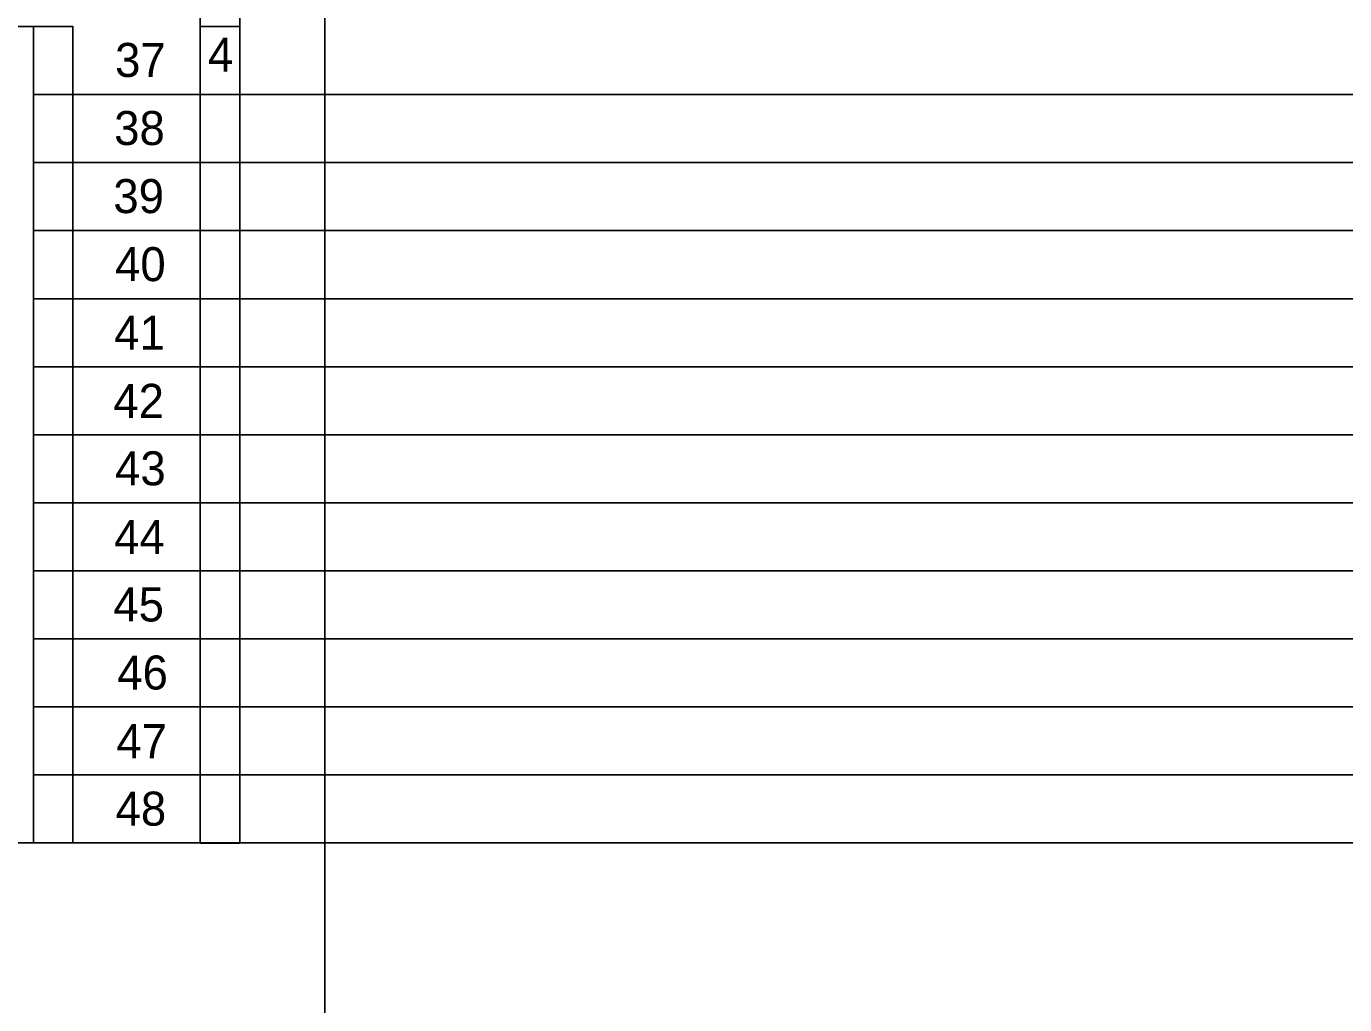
# Model space of a CAD drawing. Extents: x 1901 to 2519, y -3585 to -3154.
# Drawn here: x 2113 to 2181.2, y -3380.3 to -3329.7 of the extents above; entities that cross this region are included whole.
import ezdxf

# ---------------------------------------------------------------- set-up
doc = ezdxf.new("R2010")
doc.units = 0
doc.layers.add('rozvláknění', color=7, linetype='Continuous')

msp = doc.modelspace()

# ---------------------------------------------------------------- linework, layer by layer
at = {"layer": 'rozvláknění'}
for p, q in [((2115.435, -3333.247), (2247.063, -3333.246)), ((2115.435, -3336.765), (2247.063, -3336.764)), ((2115.435, -3340.283), (2247.063, -3340.282)), ((2115.435, -3343.801), (2247.063, -3343.8)), ((2115.435, -3347.319), (2247.063, -3347.318)), ((2115.435, -3350.837), (2247.063, -3350.837)), ((2115.435, -3354.356), (2247.063, -3354.355)), ((2115.435, -3357.874), (2247.063, -3357.873)), ((2115.435, -3361.392), (2247.063, -3361.391)), ((2115.435, -3364.91), (2247.063, -3364.909)), ((2115.435, -3368.428), (2247.063, -3368.428)), ((2115.435, -3371.947), (2247.063, -3371.946))]:
    msp.add_line(p, q, dxfattribs=at)
for points in [[(2094.462, -3178.545), (2128.46, -3178.544), (2128.46, -3571.465), (2094.462, -3571.465)], [(2124.059, -3371.961), (2122.017, -3371.961), (2122.017, -3287.488), (2124.059, -3287.488)], [(2110.606, -3329.728), (2113.393, -3329.728), (2113.393, -3371.943), (2110.606, -3371.943)], [(2113.393, -3329.728), (2115.435, -3329.728), (2115.435, -3333.247), (2113.393, -3333.247)], [(2113.393, -3329.728), (2115.435, -3329.728), (2115.435, -3333.247), (2113.393, -3333.247)], [(2124.059, -3371.947), (2122.017, -3371.947), (2122.017, -3329.728), (2124.059, -3329.728)], [(2113.393, -3333.247), (2115.435, -3333.247), (2115.435, -3336.765), (2113.393, -3336.765)], [(2113.393, -3333.247), (2115.435, -3333.247), (2115.435, -3336.765), (2113.393, -3336.765)], [(2113.393, -3336.765), (2115.435, -3336.765), (2115.435, -3340.283), (2113.393, -3340.283)], [(2113.393, -3336.765), (2115.435, -3336.765), (2115.435, -3340.283), (2113.393, -3340.283)], [(2113.393, -3340.283), (2115.435, -3340.283), (2115.435, -3343.801), (2113.393, -3343.801)], [(2113.393, -3340.283), (2115.435, -3340.283), (2115.435, -3343.801), (2113.393, -3343.801)], [(2113.393, -3343.801), (2115.435, -3343.801), (2115.435, -3347.319), (2113.393, -3347.319)], [(2113.393, -3343.801), (2115.435, -3343.801), (2115.435, -3347.319), (2113.393, -3347.319)], [(2113.393, -3347.319), (2115.435, -3347.319), (2115.435, -3350.837), (2113.393, -3350.837)], [(2113.393, -3347.319), (2115.435, -3347.319), (2115.435, -3350.837), (2113.393, -3350.837)], [(2113.393, -3350.837), (2115.435, -3350.837), (2115.435, -3354.356), (2113.393, -3354.356)], [(2113.393, -3350.837), (2115.435, -3350.837), (2115.435, -3354.356), (2113.393, -3354.356)], [(2113.393, -3354.356), (2115.435, -3354.356), (2115.435, -3357.874), (2113.393, -3357.874)], [(2113.393, -3354.356), (2115.435, -3354.356), (2115.435, -3357.874), (2113.393, -3357.874)], [(2113.393, -3357.874), (2115.435, -3357.874), (2115.435, -3361.392), (2113.393, -3361.392)], [(2113.393, -3357.874), (2115.435, -3357.874), (2115.435, -3361.392), (2113.393, -3361.392)], [(2113.393, -3361.392), (2115.435, -3361.392), (2115.435, -3364.91), (2113.393, -3364.91)], [(2113.393, -3361.392), (2115.435, -3361.392), (2115.435, -3364.91), (2113.393, -3364.91)], [(2113.393, -3364.91), (2115.435, -3364.91), (2115.435, -3368.428), (2113.393, -3368.428)], [(2113.393, -3364.91), (2115.435, -3364.91), (2115.435, -3368.428), (2113.393, -3368.428)], [(2113.393, -3368.428), (2115.435, -3368.428), (2115.435, -3371.947), (2113.393, -3371.947)], [(2113.393, -3368.428), (2115.435, -3368.428), (2115.435, -3371.947), (2113.393, -3371.947)]]:
    msp.add_lwpolyline(points, close=True, dxfattribs=at)
for points in [[(2113.393, -3333.247), (2115.435, -3333.247), (2115.435, -3329.728), (2113.393, -3329.728), (2113.393, -3333.247)], [(2113.393, -3333.247), (2115.435, -3333.247), (2115.435, -3329.728), (2113.393, -3329.728), (2113.393, -3333.247)], [(2113.393, -3333.247), (2115.435, -3333.247), (2115.435, -3329.728), (2113.393, -3329.728), (2113.393, -3333.247)], [(2113.393, -3333.247), (2115.435, -3333.247), (2115.435, -3329.728), (2113.393, -3329.728), (2113.393, -3333.247)], [(2113.393, -3333.247), (2115.435, -3333.247), (2115.435, -3329.728), (2113.393, -3329.728), (2113.393, -3333.247)], [(2113.393, -3333.247), (2115.435, -3333.247), (2115.435, -3329.728), (2113.393, -3329.728), (2113.393, -3333.247)], [(2113.393, -3333.247), (2115.435, -3333.247), (2115.435, -3329.728), (2113.393, -3329.728), (2113.393, -3333.247)], [(2113.393, -3333.247), (2115.435, -3333.247), (2115.435, -3329.728), (2113.393, -3329.728), (2113.393, -3333.247)], [(2113.393, -3333.247), (2115.435, -3333.247), (2115.435, -3329.728), (2113.393, -3329.728), (2113.393, -3333.247)], [(2113.393, -3333.247), (2115.435, -3333.247), (2115.435, -3329.728), (2113.393, -3329.728), (2113.393, -3333.247)], [(2124.059, -3329.728), (2122.017, -3329.728), (2122.017, -3371.947), (2124.059, -3371.947), (2124.059, -3329.728)], [(2124.059, -3329.728), (2122.017, -3329.728), (2122.017, -3371.947), (2124.059, -3371.947), (2124.059, -3329.728)], [(2124.059, -3329.728), (2122.017, -3329.728), (2122.017, -3371.947), (2124.059, -3371.947), (2124.059, -3329.728)], [(2124.059, -3329.728), (2122.017, -3329.728), (2122.017, -3371.947), (2124.059, -3371.947), (2124.059, -3329.728)], [(2124.059, -3329.728), (2122.017, -3329.728), (2122.017, -3371.947), (2124.059, -3371.947), (2124.059, -3329.728)], [(2124.059, -3329.728), (2122.017, -3329.728), (2122.017, -3371.947), (2124.059, -3371.947), (2124.059, -3329.728)], [(2113.393, -3333.244), (2113.393, -3368.444)], [(2113.393, -3336.765), (2115.435, -3336.765), (2115.435, -3333.247), (2113.393, -3333.247), (2113.393, -3336.765)], [(2113.393, -3336.765), (2115.435, -3336.765), (2115.435, -3333.247), (2113.393, -3333.247), (2113.393, -3336.765)], [(2113.393, -3336.765), (2115.435, -3336.765), (2115.435, -3333.247), (2113.393, -3333.247), (2113.393, -3336.765)], [(2113.393, -3336.765), (2115.435, -3336.765), (2115.435, -3333.247), (2113.393, -3333.247), (2113.393, -3336.765)], [(2113.393, -3336.765), (2115.435, -3336.765), (2115.435, -3333.247), (2113.393, -3333.247), (2113.393, -3336.765)], [(2113.393, -3336.765), (2115.435, -3336.765), (2115.435, -3333.247), (2113.393, -3333.247), (2113.393, -3336.765)], [(2113.393, -3336.765), (2115.435, -3336.765), (2115.435, -3333.247), (2113.393, -3333.247), (2113.393, -3336.765)], [(2113.393, -3336.765), (2115.435, -3336.765), (2115.435, -3333.247), (2113.393, -3333.247), (2113.393, -3336.765)], [(2113.393, -3336.765), (2115.435, -3336.765), (2115.435, -3333.247), (2113.393, -3333.247), (2113.393, -3336.765)], [(2113.393, -3336.765), (2115.435, -3336.765), (2115.435, -3333.247), (2113.393, -3333.247), (2113.393, -3336.765)], [(2113.393, -3340.283), (2115.435, -3340.283), (2115.435, -3336.765), (2113.393, -3336.765), (2113.393, -3340.283)], [(2113.393, -3340.283), (2115.435, -3340.283), (2115.435, -3336.765), (2113.393, -3336.765), (2113.393, -3340.283)], [(2113.393, -3340.283), (2115.435, -3340.283), (2115.435, -3336.765), (2113.393, -3336.765), (2113.393, -3340.283)], [(2113.393, -3340.283), (2115.435, -3340.283), (2115.435, -3336.765), (2113.393, -3336.765), (2113.393, -3340.283)], [(2113.393, -3340.283), (2115.435, -3340.283), (2115.435, -3336.765), (2113.393, -3336.765), (2113.393, -3340.283)], [(2113.393, -3340.283), (2115.435, -3340.283), (2115.435, -3336.765), (2113.393, -3336.765), (2113.393, -3340.283)], [(2113.393, -3340.283), (2115.435, -3340.283), (2115.435, -3336.765), (2113.393, -3336.765), (2113.393, -3340.283)], [(2113.393, -3340.283), (2115.435, -3340.283), (2115.435, -3336.765), (2113.393, -3336.765), (2113.393, -3340.283)], [(2113.393, -3340.283), (2115.435, -3340.283), (2115.435, -3336.765), (2113.393, -3336.765), (2113.393, -3340.283)], [(2113.393, -3340.283), (2115.435, -3340.283), (2115.435, -3336.765), (2113.393, -3336.765), (2113.393, -3340.283)], [(2113.393, -3343.801), (2115.435, -3343.801), (2115.435, -3340.283), (2113.393, -3340.283), (2113.393, -3343.801)], [(2113.393, -3343.801), (2115.435, -3343.801), (2115.435, -3340.283), (2113.393, -3340.283), (2113.393, -3343.801)], [(2113.393, -3343.801), (2115.435, -3343.801), (2115.435, -3340.283), (2113.393, -3340.283), (2113.393, -3343.801)], [(2113.393, -3343.801), (2115.435, -3343.801), (2115.435, -3340.283), (2113.393, -3340.283), (2113.393, -3343.801)], [(2113.393, -3343.801), (2115.435, -3343.801), (2115.435, -3340.283), (2113.393, -3340.283), (2113.393, -3343.801)], [(2113.393, -3343.801), (2115.435, -3343.801), (2115.435, -3340.283), (2113.393, -3340.283), (2113.393, -3343.801)], [(2113.393, -3343.801), (2115.435, -3343.801), (2115.435, -3340.283), (2113.393, -3340.283), (2113.393, -3343.801)], [(2113.393, -3343.801), (2115.435, -3343.801), (2115.435, -3340.283), (2113.393, -3340.283), (2113.393, -3343.801)], [(2113.393, -3343.801), (2115.435, -3343.801), (2115.435, -3340.283), (2113.393, -3340.283), (2113.393, -3343.801)], [(2113.393, -3343.801), (2115.435, -3343.801), (2115.435, -3340.283), (2113.393, -3340.283), (2113.393, -3343.801)], [(2113.393, -3347.319), (2115.435, -3347.319), (2115.435, -3343.801), (2113.393, -3343.801), (2113.393, -3347.319)], [(2113.393, -3347.319), (2115.435, -3347.319), (2115.435, -3343.801), (2113.393, -3343.801), (2113.393, -3347.319)], [(2113.393, -3347.319), (2115.435, -3347.319), (2115.435, -3343.801), (2113.393, -3343.801), (2113.393, -3347.319)], [(2113.393, -3347.319), (2115.435, -3347.319), (2115.435, -3343.801), (2113.393, -3343.801), (2113.393, -3347.319)], [(2113.393, -3347.319), (2115.435, -3347.319), (2115.435, -3343.801), (2113.393, -3343.801), (2113.393, -3347.319)], [(2113.393, -3347.319), (2115.435, -3347.319), (2115.435, -3343.801), (2113.393, -3343.801), (2113.393, -3347.319)], [(2113.393, -3347.319), (2115.435, -3347.319), (2115.435, -3343.801), (2113.393, -3343.801), (2113.393, -3347.319)], [(2113.393, -3347.319), (2115.435, -3347.319), (2115.435, -3343.801), (2113.393, -3343.801), (2113.393, -3347.319)], [(2113.393, -3347.319), (2115.435, -3347.319), (2115.435, -3343.801), (2113.393, -3343.801), (2113.393, -3347.319)], [(2113.393, -3347.319), (2115.435, -3347.319), (2115.435, -3343.801), (2113.393, -3343.801), (2113.393, -3347.319)], [(2113.393, -3350.837), (2115.435, -3350.837), (2115.435, -3347.319), (2113.393, -3347.319), (2113.393, -3350.837)], [(2113.393, -3350.837), (2115.435, -3350.837), (2115.435, -3347.319), (2113.393, -3347.319), (2113.393, -3350.837)], [(2113.393, -3350.837), (2115.435, -3350.837), (2115.435, -3347.319), (2113.393, -3347.319), (2113.393, -3350.837)], [(2113.393, -3350.837), (2115.435, -3350.837), (2115.435, -3347.319), (2113.393, -3347.319), (2113.393, -3350.837)], [(2113.393, -3350.837), (2115.435, -3350.837), (2115.435, -3347.319), (2113.393, -3347.319), (2113.393, -3350.837)], [(2113.393, -3350.837), (2115.435, -3350.837), (2115.435, -3347.319), (2113.393, -3347.319), (2113.393, -3350.837)], [(2113.393, -3350.837), (2115.435, -3350.837), (2115.435, -3347.319), (2113.393, -3347.319), (2113.393, -3350.837)], [(2113.393, -3350.837), (2115.435, -3350.837), (2115.435, -3347.319), (2113.393, -3347.319), (2113.393, -3350.837)], [(2113.393, -3350.837), (2115.435, -3350.837), (2115.435, -3347.319), (2113.393, -3347.319), (2113.393, -3350.837)], [(2113.393, -3350.837), (2115.435, -3350.837), (2115.435, -3347.319), (2113.393, -3347.319), (2113.393, -3350.837)], [(2113.393, -3354.356), (2115.435, -3354.356), (2115.435, -3350.837), (2113.393, -3350.837), (2113.393, -3354.356)], [(2113.393, -3354.356), (2115.435, -3354.356), (2115.435, -3350.837), (2113.393, -3350.837), (2113.393, -3354.356)], [(2113.393, -3354.356), (2115.435, -3354.356), (2115.435, -3350.837), (2113.393, -3350.837), (2113.393, -3354.356)], [(2113.393, -3354.356), (2115.435, -3354.356), (2115.435, -3350.837), (2113.393, -3350.837), (2113.393, -3354.356)], [(2113.393, -3354.356), (2115.435, -3354.356), (2115.435, -3350.837), (2113.393, -3350.837), (2113.393, -3354.356)], [(2113.393, -3354.356), (2115.435, -3354.356), (2115.435, -3350.837), (2113.393, -3350.837), (2113.393, -3354.356)], [(2113.393, -3354.356), (2115.435, -3354.356), (2115.435, -3350.837), (2113.393, -3350.837), (2113.393, -3354.356)], [(2113.393, -3354.356), (2115.435, -3354.356), (2115.435, -3350.837), (2113.393, -3350.837), (2113.393, -3354.356)], [(2113.393, -3354.356), (2115.435, -3354.356), (2115.435, -3350.837), (2113.393, -3350.837), (2113.393, -3354.356)], [(2113.393, -3354.356), (2115.435, -3354.356), (2115.435, -3350.837), (2113.393, -3350.837), (2113.393, -3354.356)], [(2113.393, -3357.874), (2115.435, -3357.874), (2115.435, -3354.356), (2113.393, -3354.356), (2113.393, -3357.874)], [(2113.393, -3357.874), (2115.435, -3357.874), (2115.435, -3354.356), (2113.393, -3354.356), (2113.393, -3357.874)], [(2113.393, -3357.874), (2115.435, -3357.874), (2115.435, -3354.356), (2113.393, -3354.356), (2113.393, -3357.874)], [(2113.393, -3357.874), (2115.435, -3357.874), (2115.435, -3354.356), (2113.393, -3354.356), (2113.393, -3357.874)], [(2113.393, -3357.874), (2115.435, -3357.874), (2115.435, -3354.356), (2113.393, -3354.356), (2113.393, -3357.874)], [(2113.393, -3357.874), (2115.435, -3357.874), (2115.435, -3354.356), (2113.393, -3354.356), (2113.393, -3357.874)], [(2113.393, -3357.874), (2115.435, -3357.874), (2115.435, -3354.356), (2113.393, -3354.356), (2113.393, -3357.874)], [(2113.393, -3357.874), (2115.435, -3357.874), (2115.435, -3354.356), (2113.393, -3354.356), (2113.393, -3357.874)], [(2113.393, -3357.874), (2115.435, -3357.874), (2115.435, -3354.356), (2113.393, -3354.356), (2113.393, -3357.874)], [(2113.393, -3357.874), (2115.435, -3357.874), (2115.435, -3354.356), (2113.393, -3354.356), (2113.393, -3357.874)], [(2113.393, -3361.392), (2115.435, -3361.392), (2115.435, -3357.874), (2113.393, -3357.874), (2113.393, -3361.392)], [(2113.393, -3361.392), (2115.435, -3361.392), (2115.435, -3357.874), (2113.393, -3357.874), (2113.393, -3361.392)], [(2113.393, -3361.392), (2115.435, -3361.392), (2115.435, -3357.874), (2113.393, -3357.874), (2113.393, -3361.392)], [(2113.393, -3361.392), (2115.435, -3361.392), (2115.435, -3357.874), (2113.393, -3357.874), (2113.393, -3361.392)], [(2113.393, -3361.392), (2115.435, -3361.392), (2115.435, -3357.874), (2113.393, -3357.874), (2113.393, -3361.392)], [(2113.393, -3361.392), (2115.435, -3361.392), (2115.435, -3357.874), (2113.393, -3357.874), (2113.393, -3361.392)], [(2113.393, -3361.392), (2115.435, -3361.392), (2115.435, -3357.874), (2113.393, -3357.874), (2113.393, -3361.392)], [(2113.393, -3361.392), (2115.435, -3361.392), (2115.435, -3357.874), (2113.393, -3357.874), (2113.393, -3361.392)], [(2113.393, -3361.392), (2115.435, -3361.392), (2115.435, -3357.874), (2113.393, -3357.874), (2113.393, -3361.392)], [(2113.393, -3361.392), (2115.435, -3361.392), (2115.435, -3357.874), (2113.393, -3357.874), (2113.393, -3361.392)], [(2113.393, -3364.91), (2115.435, -3364.91), (2115.435, -3361.392), (2113.393, -3361.392), (2113.393, -3364.91)], [(2113.393, -3364.91), (2115.435, -3364.91), (2115.435, -3361.392), (2113.393, -3361.392), (2113.393, -3364.91)], [(2113.393, -3364.91), (2115.435, -3364.91), (2115.435, -3361.392), (2113.393, -3361.392), (2113.393, -3364.91)], [(2113.393, -3364.91), (2115.435, -3364.91), (2115.435, -3361.392), (2113.393, -3361.392), (2113.393, -3364.91)], [(2113.393, -3364.91), (2115.435, -3364.91), (2115.435, -3361.392), (2113.393, -3361.392), (2113.393, -3364.91)], [(2113.393, -3364.91), (2115.435, -3364.91), (2115.435, -3361.392), (2113.393, -3361.392), (2113.393, -3364.91)], [(2113.393, -3364.91), (2115.435, -3364.91), (2115.435, -3361.392), (2113.393, -3361.392), (2113.393, -3364.91)], [(2113.393, -3364.91), (2115.435, -3364.91), (2115.435, -3361.392), (2113.393, -3361.392), (2113.393, -3364.91)], [(2113.393, -3364.91), (2115.435, -3364.91), (2115.435, -3361.392), (2113.393, -3361.392), (2113.393, -3364.91)], [(2113.393, -3364.91), (2115.435, -3364.91), (2115.435, -3361.392), (2113.393, -3361.392), (2113.393, -3364.91)], [(2113.393, -3368.428), (2115.435, -3368.428), (2115.435, -3364.91), (2113.393, -3364.91), (2113.393, -3368.428)], [(2113.393, -3368.428), (2115.435, -3368.428), (2115.435, -3364.91), (2113.393, -3364.91), (2113.393, -3368.428)], [(2113.393, -3368.428), (2115.435, -3368.428), (2115.435, -3364.91), (2113.393, -3364.91), (2113.393, -3368.428)], [(2113.393, -3368.428), (2115.435, -3368.428), (2115.435, -3364.91), (2113.393, -3364.91), (2113.393, -3368.428)], [(2113.393, -3368.428), (2115.435, -3368.428), (2115.435, -3364.91), (2113.393, -3364.91), (2113.393, -3368.428)], [(2113.393, -3368.428), (2115.435, -3368.428), (2115.435, -3364.91), (2113.393, -3364.91), (2113.393, -3368.428)], [(2113.393, -3368.428), (2115.435, -3368.428), (2115.435, -3364.91), (2113.393, -3364.91), (2113.393, -3368.428)], [(2113.393, -3368.428), (2115.435, -3368.428), (2115.435, -3364.91), (2113.393, -3364.91), (2113.393, -3368.428)], [(2113.393, -3368.428), (2115.435, -3368.428), (2115.435, -3364.91), (2113.393, -3364.91), (2113.393, -3368.428)], [(2113.393, -3368.428), (2115.435, -3368.428), (2115.435, -3364.91), (2113.393, -3364.91), (2113.393, -3368.428)], [(2113.393, -3371.947), (2115.435, -3371.947), (2115.435, -3368.428), (2113.393, -3368.428), (2113.393, -3371.947)], [(2113.393, -3371.947), (2115.435, -3371.947), (2115.435, -3368.428), (2113.393, -3368.428), (2113.393, -3371.947)], [(2113.393, -3371.947), (2115.435, -3371.947), (2115.435, -3368.428), (2113.393, -3368.428), (2113.393, -3371.947)], [(2113.393, -3371.947), (2115.435, -3371.947), (2115.435, -3368.428), (2113.393, -3368.428), (2113.393, -3371.947)], [(2113.393, -3371.947), (2115.435, -3371.947), (2115.435, -3368.428), (2113.393, -3368.428), (2113.393, -3371.947)], [(2113.393, -3371.947), (2115.435, -3371.947), (2115.435, -3368.428), (2113.393, -3368.428), (2113.393, -3371.947)], [(2113.393, -3371.947), (2115.435, -3371.947), (2115.435, -3368.428), (2113.393, -3368.428), (2113.393, -3371.947)], [(2113.393, -3371.947), (2115.435, -3371.947), (2115.435, -3368.428), (2113.393, -3368.428), (2113.393, -3371.947)], [(2113.393, -3371.947), (2115.435, -3371.947), (2115.435, -3368.428), (2113.393, -3368.428), (2113.393, -3371.947)], [(2113.393, -3371.947), (2115.435, -3371.947), (2115.435, -3368.428), (2113.393, -3368.428), (2113.393, -3371.947)]]:
    msp.add_lwpolyline(points, dxfattribs=at)

# ---------------------------------------------------------------- texts
for s, p in [('4', (2122.416, -3332.054)), ('4', (2122.416, -3332.054)), ('37', (2117.615, -3332.335)), ('38', (2117.568, -3335.855)), ('39', (2117.526, -3339.375)), ('40', (2117.615, -3342.895)), ('41', (2117.568, -3346.445)), ('42', (2117.526, -3349.965)), ('43', (2117.615, -3353.455)), ('44', (2117.568, -3357.005)), ('45', (2117.526, -3360.495)), ('46', (2117.728, -3364.015)), ('47', (2117.682, -3367.565)), ('48', (2117.639, -3371.055))]:
    msp.add_text(s, height=1.76, dxfattribs=at).set_placement(p)

doc.saveas('drawing.dxf')
